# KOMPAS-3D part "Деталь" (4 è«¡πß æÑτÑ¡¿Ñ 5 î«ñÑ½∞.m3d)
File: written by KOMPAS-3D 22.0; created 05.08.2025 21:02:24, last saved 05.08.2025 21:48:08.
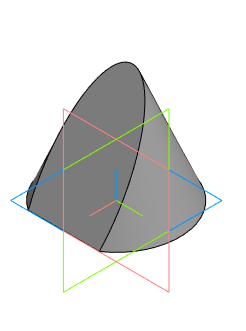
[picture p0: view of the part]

Document properties: Автор: user; Полное имя файла: G:\08 05 вторник\2025 НГ Лаб работы\Лаб 4 Сечение конуса\4 Модели\4 Конус Сечение 7 Модель.m3d

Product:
- Part/product: Деталь
    Масса: 0.416415

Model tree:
1. Эскиз:1
2. Элемент вращения:1
     Угол 1 = 360
3. Эскиз:2  (with: Элемент вращения:1)
4. Элемент выдавливания:1
     Расстояние 1 = 30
